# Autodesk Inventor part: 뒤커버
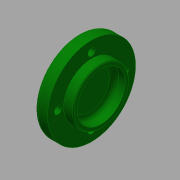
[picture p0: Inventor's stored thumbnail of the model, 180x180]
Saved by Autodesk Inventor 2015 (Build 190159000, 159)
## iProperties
Created: 2015-12
Part Number: 뒤커버
Material: 일반
Document SubType Name: Modeling
Designer: mduedu
Density: 1 g/cm^3
Appearance: 진녹색
Author: mduedu
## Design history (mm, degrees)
sketch "스케치1"
  geometry: L1 (0, 0)-(14, 0); L2 (14, 0)-(14, 17.5); L3 (14, 17.5)-(8, 17.5); L4 (8, 17.5)-(8, 27.5); L5 (8, 27.5)-(0, 27.5); L6 (0, 27.5)-(0, 0)
  constraints: 12 end point, 4 parallel, 1 horizontal, 1 perpendicular
  dimensions: "d0" = 14 distance between parallel lines of L2 L6; "d2" = 8 distance of L4.end L5.end; "d3" = 55 diameter of L5 L1; "d4" = 35 diameter of L3 L1
revolve "회전1" sketch "스케치1" stored, may be unused: angle "d5" = 90 deg
hole "구멍1" diameter "d8" = 30; stored, may be unused: countersink angle "d12" = 90 deg, drill point angle "d14" = 0 deg; dims "d9" = 6, "d10" = 4, "d11" = 2, "d13" = 7, "d39" = 10, "d40" = 10
fillet "모깎기3" dims "d38" = 2
fillet "모깎기4" dims "d41" = 3
chamfer "모따기2" distance "d42" = 0.5; stored, may be unused: second distance "d43" = 2, angle "d44" = 45 deg
sketch "스케치2" dims "d45" = 42
  geometry: 6 further points
  constraints: 2 vertical alignment, 1 coincident, 7 other
  dimensions: "d48" = 360 deg dimension on point (0, 0) point (0, 21) (derived)
sketch "스케치3"
  geometry: 4 further points
hole "구멍4" sketch "스케치3" at (-21, 0), (0, -21), (21, 0), (0, 21) diameter "d50" = 4.5; stored, may be unused: countersink angle "d54" = 90 deg, drill point angle "d56" = 0 deg; dims "d51" = 6, "d52" = 8, "d53" = 4.6, "d55" = 8
node "솔리드1"
